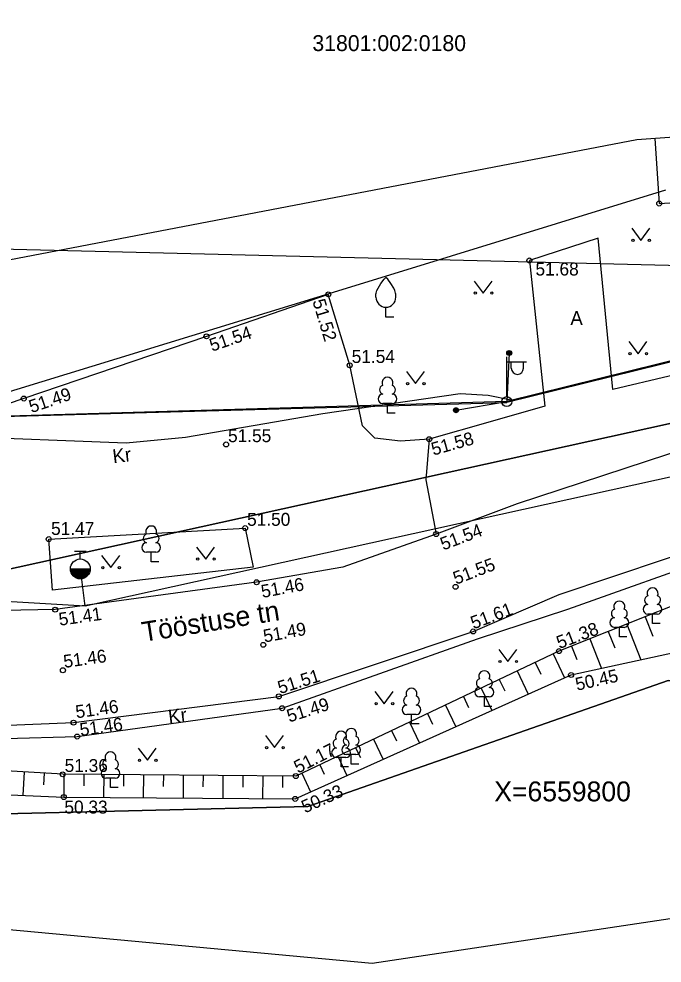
# Model space of a CAD drawing. Extents: x 542320 to 543602, y 6558748 to 6559969.
# Drawn here: x 543014.97 to 543047.34, y 6559791.38 to 6559838.87 of the extents above; entities that cross this region are included whole.
import ezdxf

# ---------------------------------------------------------------- set-up
doc = ezdxf.new("R2010")
doc.units = 0
for name, color, linetype in [('AED', 7, 'Continuous'), ('HALJASTUS', 7, 'Continuous'), ('HOONEDET', 7, 'Continuous'), ('KORGUS-EH2000', 7, 'Continuous'), ('mootpiir', 7, 'Continuous'), ('MPKAABEL', 7, 'Continuous'), ('MPOHULIIN', 7, 'Continuous'), ('PIIR', 7, 'Continuous'), ('POST', 7, 'Continuous'), ('PUU', 7, 'Continuous'), ('RELJEEF', 7, 'Continuous'), ('SIOHULIIN', 7, 'Continuous'), ('TEE', 7, 'Continuous'), ('VEEKOGU', 7, 'Continuous'), ('VKAEV', 7, 'Continuous'), ('VORK', 7, 'Continuous'), ('VTRASS', 7, 'Continuous')]:
    doc.layers.add(name, color=color, linetype=linetype)

# ---------------------------------------------------------------- blocks, each defined once
blk = doc.blocks.new('VILJA1')
for p, q in [((0, 0), (0, 1)), ((0.8, 0), (0, 0))]:
    blk.add_line(p, q)
for points in [[(-1, 2), (-1, 2.3), (-0.98, 2.43), (-0.91, 2.69), (-0.79, 2.93), (-0.5, 3.4), (-0.18, 3.81), (0, 4)], [(1, 2), (1, 2.3), (0.98, 2.43), (0.91, 2.69), (0.79, 2.93), (0.5, 3.4), (0.18, 3.81), (0, 4)]]:
    blk.add_lwpolyline(points)
blk.add_arc((0, 2), 1, 180, 0)
blk = doc.blocks.new('THYDRM')
for p, q in [((-0.6, 1.8), (0.6, 1.8)), ((0, 1), (0, 1.8)), ((-1, 0), (1, 0))]:
    blk.add_line(p, q)
blk.add_circle((0, 0), 1)
for radius in [0.959, 0.917, 0.876, 0.834, 0.793, 0.751, 0.71, 0.668, 0.627, 0.585, 0.544, 0.502, 0.461, 0.419, 0.378, 0.336, 0.295, 0.253, 0.212, 0.17, 0.129, 0.0871, 0.0457]:
    blk.add_arc((0, 0), radius, 180, 0)
blk = doc.blocks.new('PUPOST')
blk.add_circle((0, 0), 0.5)
blk = doc.blocks.new('LEHTP1')
for p, q in [((0.48, 0.95), (-0.48, 0.95)), ((0, 0), (0, 0.95)), ((0.76, 0), (0, 0))]:
    blk.add_line(p, q)
for centre, radius, start, end in [((0, 3.04), 0.554, 332.5799, 207.4201), ((-0.475, 1.425), 0.475, 90.0016, 269.3953), ((-0.34, 2.345), 0.465, 109.02174, 253.14154), ((0.34, 2.345), 0.465, 286.85082, 70.98591), ((0.475, 1.425), 0.475, 270.6047, 89.9984)]:
    blk.add_arc(centre, radius, start, end)
blk = doc.blocks.new('ANKURP')
for radius in [0.25, 0.234, 0.219, 0.203, 0.188, 0.172, 0.156, 0.141, 0.125, 0.11, 0.0939, 0.0783, 0.0628, 0.0472, 0.0316, 0.016, 0.000371]:
    blk.add_circle((0, 0), radius)
blk = doc.blocks.new('MURU')
for p, q in [((-0.927, 1.213), (0, 0)), ((0, 0), (0.891, 1.213))]:
    blk.add_line(p, q)
for centre in [(-0.802, 0), (0.856, 0)]:
    blk.add_circle(centre, 0.11)
blk = doc.blocks.new('VAPOST')
for p, q in [((0, 0.5), (0, 4.5)), ((0, 4), (2, 4)), ((0.453, 3.358), (0.453, 4)), ((1.679, 3.358), (1.679, 4))]:
    blk.add_line(p, q)
blk.add_arc((1.066, 3.358), 0.613, 180, 0)
blk = doc.blocks.new('RING02')
blk.add_circle((0, 0), 0.25)

msp = doc.modelspace()

# ---------------------------------------------------------------- linework, layer by layer
at = {"layer": 'AED'}
msp.add_lwpolyline([(543047.506, 6559830.252), (543031.229, 6559825.246), (543011.07, 6559819.081), (543008.098, 6559818.456), (543001.026, 6559817.957)], dxfattribs=at)
at = {"layer": 'HOONEDET'}
msp.add_lwpolyline([(543046.969, 6559832.855), (543047.191, 6559829.582), (543058.866, 6559830.32), (543058.88, 6559830.819)], dxfattribs=at)
at = {"layer": 'mootpiir'}
msp.add_lwpolyline([(543090.147, 6559835.076), (543086.631, 6559835.669), (543046.075, 6559832.791), (542960.087, 6559816.316), (542958.508, 6559813.972), (542958.352, 6559813.615), (542958.072, 6559811.407), (542958.097, 6559811.262), (542958.667, 6559807.427), (542958.816, 6559803.633), (542958.4, 6559802.481), (542958.245, 6559799.726), (542966.032, 6559797.567), (543032.743, 6559791.379), (543093.076, 6559800.414), (543094.129, 6559807.466), (543092.769, 6559812.064), (543093.098, 6559815.823), (543092.736, 6559818.278), (543092.585, 6559819.369), (543092.195, 6559821.683), (543090.475, 6559823.796), (543090.459, 6559823.908), (543090.312, 6559826.089)], close=True, dxfattribs=at)
at = {"layer": 'MPKAABEL'}
msp.add_lwpolyline([(543039.748, 6559819.685), (543038.588, 6559819.926), (543037.17, 6559820.01), (543030.258, 6559819.008), (543023.354, 6559817.818), (543020.365, 6559817.533), (543011.681, 6559817.864), (543006.243, 6559818.05), (543000.846, 6559817.433), (542998.993, 6559816.701), (542997.184, 6559816.239), (542989.641, 6559813.781), (542988.393, 6559813.49), (542980.759, 6559813.43), (542979.797, 6559813.172), (542976.647, 6559812.126), (542970.647, 6559810.142), (542965.94, 6559809.02), (542958.683, 6559807.008)], dxfattribs=at)
msp.add_lwpolyline([(543039.748, 6559819.685), (543038.588, 6559819.926), (543037.17, 6559820.01), (543030.258, 6559819.008), (543023.354, 6559817.818), (543020.365, 6559817.533), (543011.681, 6559817.864), (543006.243, 6559818.05), (543000.846, 6559817.433), (542998.993, 6559816.701), (542997.184, 6559816.239), (542989.641, 6559813.781), (542988.393, 6559813.49), (542980.759, 6559813.43), (542979.797, 6559813.172), (542976.647, 6559812.126), (542970.647, 6559810.142), (542965.94, 6559809.02), (542958.683, 6559807.008)], dxfattribs=at)
at = {"layer": 'MPOHULIIN'}
msp.add_lwpolyline([(543065.505, 6559826.048), (543039.523, 6559819.62), (543009.299, 6559818.737), (542961.154, 6559815.297)], dxfattribs=at)
at = {"layer": 'PIIR'}
for points in [[(542995.62, 6559810.72), (542999.42, 6559826.35), (543006.28, 6559854.63), (543022.96, 6559853.69), (543024.02, 6559863.81), (543009.03, 6559865.93), (543011.73, 6559877.03), (543035.19, 6559883.28), (543069.03, 6559887.03), (543076.83, 6559836.49), (543078.56, 6559825.31), (543011.79, 6559810.61), (542995.62, 6559810.72)], [(543110.35, 6559810.08), (543085.87, 6559802.96), (543074.33, 6559802.6), (543047.65, 6559805.6), (543029.51, 6559799.26), (543012.82, 6559798.86), (543001.44, 6559800.31), (542966.22, 6559801.72), (542946.49, 6559799.49), (542945.79, 6559811), (542995.62, 6559810.72), (543011.79, 6559810.61), (543078.56, 6559825.31), (543076.83, 6559836.49), (543087.22, 6559837.42), (543085.54, 6559829.09), (543128.04, 6559829.23)], [(543012.82, 6559798.86), (543029.51, 6559799.26), (543047.65, 6559805.6), (543074.33, 6559802.6), (543085.87, 6559802.96), (543110.35, 6559810.08)]]:
    msp.add_lwpolyline(points, dxfattribs=at)
at = {"layer": 'POST'}
for points in [[(543039.645, 6559822.065), (543039.523, 6559819.62)], [(543036.966, 6559819.187), (543039.523, 6559819.62)]]:
    msp.add_lwpolyline(points, dxfattribs=at)
at = {"layer": 'RELJEEF'}
for points in [[(543092.769, 6559812.064), (543089.999, 6559809.142), (543084.85, 6559808.813), (543080.585, 6559810.073), (543073.543, 6559810.368), (543068.572, 6559810.695), (543059.132, 6559808.528), (543057.697, 6559808.874), (543055.711, 6559810.294), (543052.162, 6559811.058), (543042.149, 6559807.07), (543028.907, 6559800.786), (543017.173, 6559800.875), (543003.671, 6559801.671), (542989.215, 6559802.013), (542980.978, 6559802.587), (542969.167, 6559801.941), (542958.4, 6559802.481)], [(543045.562, 6559808.43), (543046.277, 6559806.635)], [(543046.492, 6559808.8), (543046.88, 6559807.825)], [(543044.633, 6559808.06), (543044.96, 6559807.24)], [(543043.704, 6559807.69), (543044.296, 6559806.205)], [(543042.775, 6559807.319), (543043.04, 6559806.655)], [(543041.855, 6559806.93), (543042.428, 6559805.722)], [(543040.048, 6559806.073), (543040.603, 6559804.903)], [(543040.951, 6559806.502), (543041.233, 6559805.907)], [(543039.144, 6559805.644), (543039.417, 6559805.069)], [(543038.241, 6559805.215), (543038.778, 6559804.084)], [(543037.338, 6559804.787), (543037.602, 6559804.23)], [(543036.434, 6559804.358), (543036.953, 6559803.265)], [(543035.531, 6559803.929), (543035.786, 6559803.392)], [(543034.627, 6559803.501), (543035.128, 6559802.446)], [(543033.724, 6559803.072), (543033.97, 6559802.554)], [(543032.82, 6559802.643), (543033.303, 6559801.626)], [(543031.014, 6559801.786), (543031.478, 6559800.807)], [(543031.917, 6559802.214), (543032.154, 6559801.716)], [(543030.11, 6559801.357), (543030.338, 6559800.877)], [(543015.242, 6559800.989), (543015.173, 6559799.818)], [(543016.241, 6559800.93), (543016.207, 6559800.353)], [(543017.239, 6559800.874), (543017.23, 6559799.73)], [(543018.239, 6559800.867), (543018.235, 6559800.295)], [(543019.239, 6559800.859), (543019.23, 6559799.714)], [(543020.239, 6559800.852), (543020.235, 6559800.279)], [(543021.239, 6559800.844), (543021.23, 6559799.699)], [(543022.239, 6559800.837), (543022.235, 6559800.264)], [(543023.239, 6559800.829), (543023.23, 6559799.683)], [(543024.239, 6559800.821), (543024.234, 6559800.248)], [(543029.207, 6559800.928), (543029.653, 6559799.988)], [(543025.239, 6559800.814), (543025.23, 6559799.667)], [(543026.239, 6559800.806), (543026.234, 6559800.233)], [(543027.239, 6559800.799), (543027.23, 6559799.652)], [(543028.239, 6559800.791), (543028.234, 6559800.218)]]:
    msp.add_lwpolyline(points, dxfattribs=at)
at = {"layer": 'SIOHULIIN'}
for points in [[(542986.521, 6559827.98), (543065.505, 6559826.048), (543087.322, 6559835.539)], [(543065.564, 6559825.995), (543039.532, 6559819.569)], [(543009.299, 6559818.737), (543039.532, 6559819.569)]]:
    msp.add_lwpolyline(points, dxfattribs=at)
at = {"layer": 'TEE'}
for points in [[(543059.834, 6559822.98), (543055.462, 6559822.59), (543053.469, 6559822.365), (543052.979, 6559822.974), (543052.571, 6559823.736), (543051.452, 6559824.494), (543047.774, 6559824.845), (543048.484, 6559821.084), (543047.702, 6559820.894), (543044.868, 6559820.228), (543044.116, 6559827.845), (543040.658, 6559826.72), (543041.446, 6559819.386), (543038.689, 6559818.611), (543035.622, 6559817.731), (543035.443, 6559815.688), (543035.967, 6559812.959)], [(543035.622, 6559817.731), (543034.167, 6559817.635), (543032.883, 6559817.779), (543032.269, 6559818.41), (543031.618, 6559821.447), (543030.542, 6559825.015), (543024.408, 6559822.902), (543015.216, 6559819.776), (543006.711, 6559816.894), (542998.482, 6559815.34), (542996.823, 6559813.441)], [(543060.355, 6559820.503), (543057.468, 6559819.65), (543048.685, 6559817.313), (543040.045, 6559814.486), (543035.967, 6559812.959), (543031.279, 6559811.296), (543026.934, 6559810.533), (543016.801, 6559809.157), (543007.227, 6559808.975), (542997.411, 6559809.534), (542988.775, 6559810.531)], [(542958.816, 6559803.633), (542969.162, 6559804.651), (542980.925, 6559804.056), (542987.926, 6559803.597), (542997.513, 6559803.059), (543007.107, 6559803.04), (543017.723, 6559803.474), (543028.051, 6559804.793), (543037.828, 6559808.06), (543042.163, 6559809.918), (543050.261, 6559812.635), (543059.043, 6559815.346), (543068.835, 6559817.386), (543079.318, 6559818.681), (543092.585, 6559819.369)], [(542997.513, 6559803.059), (543007.066, 6559802.483), (543017.906, 6559802.775), (543028.213, 6559804.2), (543038.057, 6559807.69), (543042.598, 6559809.18), (543050.432, 6559811.965), (543059.255, 6559814.566), (543068.982, 6559816.272), (543079.524, 6559817.38), (543092.736, 6559818.278)], [(543016.655, 6559810.141), (543016.655, 6559810.141), (543016.47, 6559812.704), (543026.354, 6559813.256), (543026.755, 6559811.29), (543016.655, 6559810.141)]]:
    msp.add_lwpolyline(points, dxfattribs=at)
at = {"layer": 'VEEKOGU'}
msp.add_lwpolyline([(542958.245, 6559799.726), (542969.193, 6559799.837), (542980.767, 6559800.499), (542989.253, 6559800.672), (543003.747, 6559800.309), (543017.23, 6559799.73), (543028.875, 6559799.639), (543042.762, 6559805.872), (543054.415, 6559808.402), (543057.212, 6559806.164), (543069.386, 6559808.821), (543079.867, 6559807.81), (543085.814, 6559807.064), (543094.129, 6559807.466)], dxfattribs=at)
at = {"layer": 'VTRASS'}
for points in [[(543084.909, 6559820.815), (543050.322, 6559816.388), (543018.303, 6559809.334), (542995.998, 6559810.646), (542958.256, 6559810.221)], [(543018.06, 6559811.205), (543018.292, 6559809.331)]]:
    msp.add_lwpolyline(points, dxfattribs=at)

# ---------------------------------------------------------------- block references
at = {"layer": 'HALJASTUS', "xscale": 0.5, "yscale": 0.5}
for p in [(543046.272, 6559827.732), (543038.341, 6559825.079), (543046.129, 6559822.031), (543034.932, 6559820.524), (543024.371, 6559811.701), (543019.597, 6559811.273), (543039.581, 6559806.548), (543033.352, 6559804.426), (543027.839, 6559802.218), (543021.439, 6559801.58)]:
    msp.add_blockref('MURU', p, dxfattribs=at)
at = {"layer": 'KORGUS-EH2000', "xscale": 0.5, "yscale": 0.5}
for p in [(543047.191, 6559829.582), (543040.658, 6559826.72), (543030.542, 6559825.015), (543024.408, 6559822.902), (543031.618, 6559821.447), (543015.216, 6559819.776), (543025.395, 6559817.465), (543035.622, 6559817.731), (543026.354, 6559813.256), (543016.47, 6559812.704), (543035.967, 6559812.959), (543026.934, 6559810.533), (543036.946, 6559810.304), (543016.801, 6559809.157), (543037.828, 6559808.06), (543027.269, 6559807.387), (543042.149, 6559807.07), (543017.187, 6559806.109), (543042.762, 6559805.872), (543028.051, 6559804.793), (543028.213, 6559804.2), (543017.723, 6559803.474), (543017.906, 6559802.775), (543017.173, 6559800.875), (543028.907, 6559800.786), (543017.23, 6559799.73), (543028.875, 6559799.639)]:
    msp.add_blockref('RING02', p, dxfattribs=at)
at = {"layer": 'POST', "xscale": 0.5, "yscale": 0.5}
for name, p in [('ANKURP', (543039.645, 6559822.065)), ('VAPOST', (543039.523, 6559819.62)), ('PUPOST', (543039.523, 6559819.62)), ('ANKURP', (543036.966, 6559819.187))]:
    msp.add_blockref(name, p, dxfattribs=at)
at = {"layer": 'PUU', "xscale": 0.5, "yscale": 0.5}
for name, p in [('VILJA1', (543033.44, 6559823.868)), ('LEHTP1', (543033.519, 6559819.045)), ('LEHTP1', (543021.628, 6559811.566)), ('LEHTP1', (543046.859, 6559808.46)), ('LEHTP1', (543045.187, 6559807.791)), ('LEHTP1', (543038.395, 6559804.289)), ('LEHTP1', (543034.728, 6559803.407)), ('LEHTP1', (543031.693, 6559801.389)), ('LEHTP1', (543031.185, 6559801.248)), ('LEHTP1', (543019.579, 6559800.207))]:
    msp.add_blockref(name, p, dxfattribs=at)
at = {"layer": 'VKAEV', "xscale": 0.5, "yscale": 0.5}
msp.add_blockref('THYDRM', (543018.06, 6559811.205), dxfattribs=at)

# ---------------------------------------------------------------- texts
at = {"layer": 'KORGUS-EH2000'}
for s, p in [('51.68', (543040.967, 6559825.963)), ('51.54', (543031.718, 6559821.564)), ('51.55', (543025.495, 6559817.582)), ('51.50', (543026.454, 6559813.373)), ('51.47', (543016.59, 6559812.913)), ('51.36', (543017.273, 6559800.992)), ('50.33', (543017.26, 6559798.903))]:
    msp.add_text(s, height=0.65, dxfattribs=at).set_placement(p)
for s, rotation, p in [('51.52', 286.7579, (543029.737, 6559824.674)), ('51.54', 18.7389, (543024.69, 6559822.128)), ('51.49', 18.6819, (543015.604, 6559819.039)), ('51.58', 15.7137, (543035.826, 6559816.902)), ('51.54', 20.7182, (543036.324, 6559812.127)), ('51.55', 20.7182, (543036.969, 6559810.407)), ('51.46', 10.4483, (543027.221, 6559809.743)), ('51.61', 20.7182, (543037.851, 6559808.163)), ('51.41', 7.9031, (543017.019, 6559808.346)), ('51.49', 10.4483, (543027.33, 6559807.5)), ('51.38', 20.7182, (543042.172, 6559807.173)), ('51.46', 7.9031, (543017.257, 6559806.224)), ('51.51', 17.5427, (543028.114, 6559804.907)), ('50.45', 12.5356, (543043.054, 6559805.075)), ('51.46', 7.9031, (543017.864, 6559803.69)), ('51.49', 17.5427, (543028.572, 6559803.477)), ('51.46', 7.9031, (543018.077, 6559802.797)), ('51.17', 26.8643, (543029.015, 6559800.904)), ('50.33', 24.3688, (543029.372, 6559798.904))]:
    msp.add_text(s, height=0.65, rotation=rotation, dxfattribs=at).set_placement(p)
at = {"layer": 'PIIR'}
msp.add_text('31801:002:0180', height=0.8, dxfattribs=at).set_placement((543029.738, 6559837.251))
at = {"layer": 'TEE'}
msp.add_text('A', height=0.7, dxfattribs=at).set_placement((543042.723, 6559823.473))
for s, height, rotation, p in [('Kr', 0.7, 6.9919, (543019.725, 6559816.518)), ('Tööstuse tn', 1, 9.0416, (543021.242, 6559807.534)), ('Kr', 0.7, 6.9919, (543022.527, 6559803.42))]:
    msp.add_text(s, height=height, rotation=rotation, dxfattribs=at).set_placement(p)
at = {"layer": 'VORK'}
msp.add_text('X=6559800', height=1, dxfattribs=at).set_placement((543038.891, 6559799.515))

doc.saveas('drawing.dxf')
